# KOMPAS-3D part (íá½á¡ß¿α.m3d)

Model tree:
1. Смещенная плоскость:1
     Расстояние = 15
2. Эскиз:23
3. Операция выдавливания:17
     Расстояние 1 = 1; Угол 1 = 20
4. Эскиз:24
5. Операция выдавливания:18
     Расстояние 1 = 1; Угол 1 = 17.2
6. Эскиз:26
7. Операция выдавливания:19
     Расстояние 1 = 2.2
8. Эскиз:27
9. Операция выдавливания:20
     Расстояние 1 = 2.2
10. Эскиз:28
11. Операция выдавливания:21
     Расстояние 1 = 4.2; Расстояние 2 = 3.2
12. Эскиз:29
13. Отверстие:3
14. Эскиз:30
15. Вырезать элемент выдавливания:3
     Расстояние 1 = 3.2
16. Скругление:13
     Радиус = 1
17. Скругление:14
     Радиус = 1
18. Скругление:15
     Радиус = 0.5
19. Скругление:16
     Радиус = 0.5
20. Скругление:17
     Радиус = 0.5
21. Эскиз:31
22. Операция выдавливания:22
     Расстояние 1 = 1; Расстояние 2 = 1
23. Эскиз:32
24. Операция выдавливания:23
     Расстояние 1 = 1; Расстояние 2 = 1
25. Эскиз:33
26. Вырезать элемент выдавливания:4
     Расстояние 1 = 1
27. Скругление:18
     Радиус = 1
28. Скругление:19
     Радиус = 0.5
29. Условное изображение резьбы:5
     Длина резьбы = 3.2; Шаг резьбы = 1; Номинальный диаметр резьбы = 4.88253
30. Условное изображение резьбы:6
     Длина резьбы = 3.2; Шаг резьбы = 1; Номинальный диаметр резьбы = 5.88253

Referenced files in C:\Program Files\ASCON\KOMPAS-3D V13 Home\Sys\: holelib.lfr
Referenced files in C:\Program Files\ASCON\KOMPAS-3D V12\Sys\: holelib.lfr
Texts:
  Сплав АЛ8  ГОСТ 1583-93
  Отверстие 01
  (вариант 1)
